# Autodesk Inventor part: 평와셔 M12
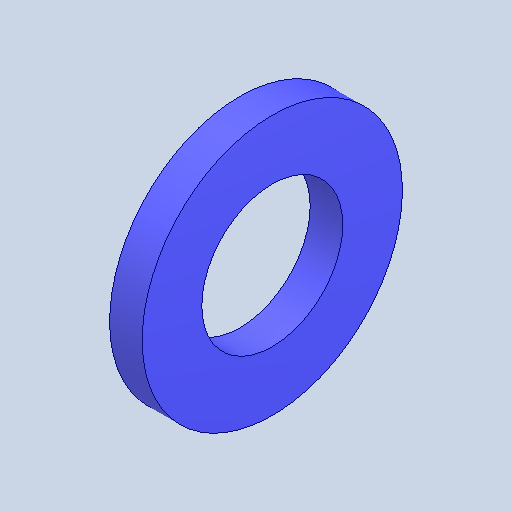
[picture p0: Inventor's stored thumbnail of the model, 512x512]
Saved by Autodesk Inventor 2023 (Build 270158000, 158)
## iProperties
Created: 2025-03
Part Number: 평와셔 M12
Material: 스테인리스강
Description: 평면 와셔
Document SubType Name: Modeling
Designer: ADMIN_PC
Density: 8.08 g/cm^3
Appearance: 기본값
Author: jhkim
Sending System: Autodesk Inventor 2025
Preprocessor: ST-DEVELOPER v20
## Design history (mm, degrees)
feature "Solid1"
node "솔리드1"
